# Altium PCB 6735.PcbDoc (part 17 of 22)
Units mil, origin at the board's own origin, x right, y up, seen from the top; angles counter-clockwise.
Board outline 2641.73 x 5165.35 mil, 6 copper layers (Top, Inner Layer 2, Inner Layer 3, Inner Layer 4, Inner Layer 5, Bottom), stack 35.7 mil thick; 1011 components, 790 nets, 4118 pads, 9325 vias.
Unrouted connection lines stored in the file: 4610.
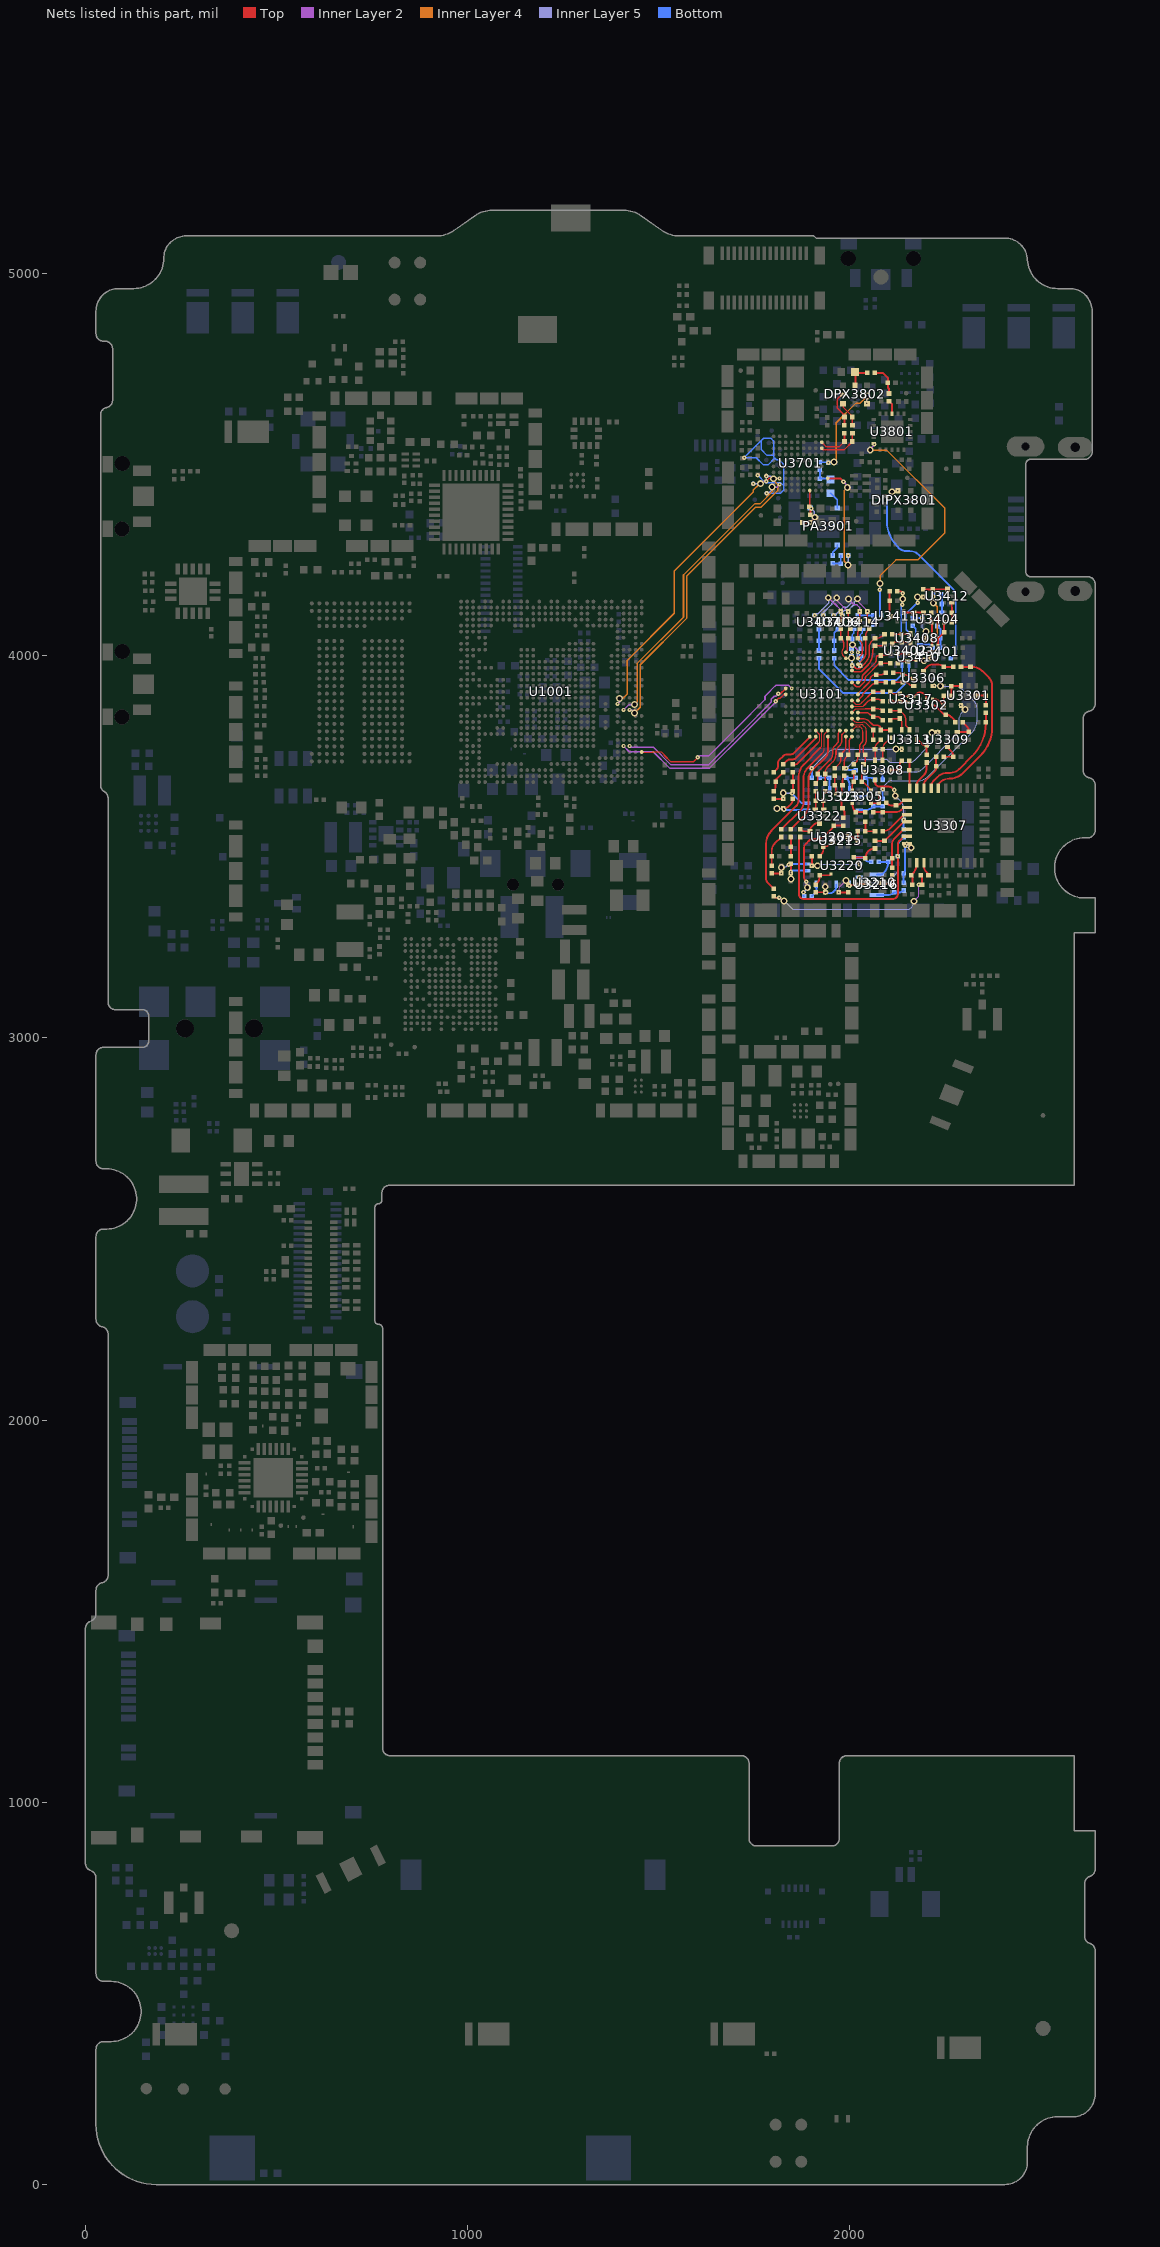
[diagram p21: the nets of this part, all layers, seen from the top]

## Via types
v1: diameter 12, hole 4, Top to Inner Layer 2, 3329 vias
v2: diameter 12, hole 4, Inner Layer 5 to Bottom, 3071 vias
v3: diameter 18, hole 10, Inner Layer 2 to Inner Layer 5, 1928 vias
v4: diameter 10, hole 4, Top to Inner Layer 2, 525 vias
v5: diameter 20, hole 12, Top to Bottom, 472 vias

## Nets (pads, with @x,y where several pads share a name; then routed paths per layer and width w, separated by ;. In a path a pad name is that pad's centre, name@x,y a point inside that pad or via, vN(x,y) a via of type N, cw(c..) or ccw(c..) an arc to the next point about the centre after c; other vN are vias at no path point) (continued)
RF_B1_PA_DPX: C3215.1 L3206.1 U3306.3 | length 529.8
  Top w5: U3306.3@2218.24,3920.9 v1(2221.24,3920.9)
  Inner Layer 2 w3: v1(2221.24,3920.9) 2221.24,3920.75 2236.65,3920.75 v3(2236.65,3920.59)
  Inner Layer 5 w3: v2(2085.65,3650.59) 2085.65,3651.59 cw(c2095.31,3651.59) 2088.48,3658.42 2098.17,3668.11 cw(c2109,3657.28) 2109,3672.59 2178.65,3672.59 ccw(c2178.65,3705.93) 2202.23,3682.36 2321.47,3801.6 ccw(c2294.48,3828.59) 2332.65,3828.59 2332.65,3863.59 ccw(c2310.92,3863.59) 2326.29,3878.95 2295.97,3909.28 ccw(c2268.65,3881.96) 2268.65,3920.59 v3(2236.65,3920.59)
  Bottom w5: L3206.1@2085.65,3625.59 v2(2085.65,3650.59)
RF_B1_PA_PA: C3216.1 L3206.2 U3203.25 | length 64
  Bottom w5: U3203.25@2024.55,3596.26 2041.65,3596.26 ccw(c2041.65,3619.6) 2058.16,3603.1 C3216.1@2060.65,3605.59 L3206.2@2085.65,3605.59
RF_B1_PRX_DPX_RFIN1: C3325.1 L3310.2 U3306.8 | length 57.8
  Top w4: C3325.1@2113.65,3955.59 2126.69,3955.59 cw(c2126.69,3938.79) 2138.57,3950.67 L3310.2@2138.65,3950.59 2143.65,3950.59 cw(c2143.65,3940.93) 2150.48,3947.76 2152.7,3945.54 ccw(c2164.65,3957.49) 2164.65,3940.59 U3306.8@2167.06,3940.59
RF_B1_PRX_DPX_RFIP1: C3323.1 L3310.1 U3306.1 | length 56.2
  Top w4: C3323.1@2113.65,3930.59 L3310.1@2138.65,3930.59 2145.65,3930.59 cw(c2145.65,3920.93) 2152.48,3927.76 2153.94,3926.3 ccw(c2166.97,3939.32) 2166.97,3920.9 U3306.1@2167.06,3920.9
RF_B1_PRX_MT6169_RFIN1_HB3: C3325.2 L3308.2 U3101.A8 | length 101
  Top w4: U3101.A8@2021.14,3898.59 2021.14,3901.08 2049.29,3929.23 ccw(c2039.92,3938.59) 2053.17,3938.59 2053.17,3939.59 cw(c2060.41,3939.59) 2055.29,3944.71 2057.29,3946.71 cw(c2066.65,3937.35) 2066.65,3950.59 L3308.2@2068.65,3950.59 2081.65,3950.59 ccw(c2081.65,3967.49) 2093.6,3955.54 C3325.2@2093.65,3955.59
RF_B1_PRX_MT6169_RFIP1_HB3: C3323.2 L3308.1 U3101.A9 | length 94.1
  Top w4: U3101.A9@2021.14,3882.84 2032.58,3894.28 ccw(c2029.74,3897.12) 2033.75,3897.12 2033.75,3898.59 cw(c2036.41,3898.59) 2034.53,3900.47 2057.82,3923.76 cw(c2064.65,3916.93) 2064.65,3926.59 L3308.1@2068.65,3930.59 C3323.2@2093.65,3930.59
RF_B1_TRX_DPX: L3309.2 L3311.1 U3306.6 | length 86.8
  Top w5: U3306.6@2192.65,3960.28 2192.65,3961.9 2193,3961.9 2203.31,3972.22 cw(c2213.87,3961.66) 2213.87,3976.59 2232.35,3976.59 cw(c2232.35,3958.95) 2244.82,3971.42 L3311.1@2245.65,3970.59 L3309.2@2270.65,3970.59
RF_B1_TRX_TXM: L3309.1 L3351.1 U3307.26 | length 446
  Top w5: U3307.26@2231.76,3653.03 2231.76,3664.59 2235.22,3668.06 cw(c2260.65,3642.62) 2260.65,3678.59 2261.65,3678.59 ccw(c2261.65,3726.87) 2295.8,3692.73 2341.39,3738.33 ccw(c2267.13,3812.59) 2372.15,3812.59 2372.15,3922.59 ccw(c2344.39,3922.59) 2364.02,3942.22 2346.26,3959.98 ccw(c2320.65,3934.38) 2320.65,3970.59 L3351.1@2315.65,3970.59 L3309.1@2290.65,3970.59
RF_B2_PA_DPX: C3222.1 L3207.1 U3301.3 | length 348.8
  Top w5: v1(2290.65,3870.59) 2290.97,3870.28 U3301.3@2290.97,3870
  Inner Layer 2 w3: v1(2290.65,3870.59) v3(2301.65,3859.59)
  Inner Layer 5 w3: v2(2085.65,3700.59) 2086.12,3700.13 ccw(c2094.65,3708.66) 2094.65,3696.59 2171.65,3696.59 ccw(c2171.65,3722.83) 2190.21,3704.28 2279.85,3793.92 ccw(c2263.42,3810.34) 2286.65,3810.34 2286.65,3837.59 cw(c2303.55,3837.59) 2291.6,3849.54 v3(2301.65,3859.59)
  Bottom w5: L3207.1@2085.65,3675.59 v2(2085.65,3700.59)
RF_B2_PA_PA: C3223.1 L3207.2 U3203.23 | length 94.8
  Bottom w5: U3203.23@2024.55,3630.9 2032.97,3630.9 ccw(c2032.97,3644.59) 2046.65,3644.59 2046.65,3674.59 C3223.1@2040.65,3680.59 2054.65,3680.59 cw(c2054.65,3666.1) 2064.9,3676.35 L3207.2@2065.65,3675.59
RF_B2_PRX_DPX: C3302.1 L3304.1 U3301.1 | length 50.6
  Top w5: C3302.1@2265.65,3895.59 L3304.1@2265.65,3920.59 2266.24,3921.18 U3301.1@2290.97,3921.18
RF_B2_PRX_SWITCH: C3302.2 L3302.1 U3302.3 | length 59.6
  Top w5: U3302.3@2216.4,3886.34 2218.65,3886.34 cw(c2218.65,3859.17) 2237.86,3878.38 L3302.1@2245.65,3870.59 C3302.2@2245.65,3895.59
RF_B2_TRX_DPX: C3303.2 L3303.1 U3301.6 | length 50.3
  Top w5: U3301.6@2330.34,3895.59 L3303.1@2355.65,3895.59 C3303.2@2355.65,3870.59
RF_B2_TRX_TXM: C3303.1 L3301.1 U3307.27 | length 268.7
  Top w5: U3307.27@2212.86,3653.03 2212.86,3657.59 cw(c2234.59,3657.59) 2219.22,3672.95 2228.69,3682.42 cw(c2255.65,3655.46) 2255.65,3693.59 2262.65,3693.59 ccw(c2262.65,3726.05) 2285.6,3703.1 2320.12,3737.62 ccw(c2234.35,3823.39) 2355.65,3823.39 L3301.1@2355.65,3825.59 C3303.1@2355.65,3850.59
RF_B2B3_PRX_BALUN: U3302.4 U3317.2 | length 47
  Top w5: U3317.2@2168.13,3893.46 2175.15,3900.48 cw(c2182.65,3892.98) 2182.65,3903.59 2183.65,3903.59 cw(c2183.65,3884.28) 2197.31,3897.93 2197.82,3897.42 cw(c2191,3890.59) 2200.65,3890.59 U3302.4@2200.65,3886.34
RF_B2B3_PRX_BALUN_RFIN1: C3307.1 L3305.1 U3317.3 | length 51
  Top w4: C3307.1@2105.65,3905.59 2106.41,3904.83 ccw(c2116.65,3915.08) 2116.65,3900.59 L3305.1@2130.65,3900.59 2131.84,3899.4 ccw(c2146.17,3913.73) 2146.17,3893.46 U3317.3@2153.17,3893.46
RF_B2B3_PRX_BALUN_RFIP1: C3311.1 L3305.2 U3317.4 | length 48.4
  Top w4: C3311.1@2105.65,3880.59 L3305.2@2130.65,3880.59 2147.65,3880.59 cw(c2147.65,3874.2) 2152.17,3878.72 U3317.4@2153.17,3877.72
RF_B2B3_PRX_MT6169_RFIN1_MB2: C3307.2 L3335.1 U3101.B9 | length 97.4
  Top w3: U3101.B9@2005.39,3882.84 2015.14,3873.09 2023.65,3873.09 ccw(c2023.65,3881.55) 2029.63,3875.57 2031.65,3877.59
  Top w4: 2031.65,3877.59 2059.65,3905.59 L3335.1@2060.65,3905.59 C3307.2@2085.65,3905.59
RF_B2B3_PRX_MT6169_RFIP1_MB2: C3311.2 L3335.2 U3101.B10 | length 88.2
  Top w3: U3101.B10@2005.39,3867.09 2030.24,3867.09 ccw(c2030.24,3876.55) 2036.93,3869.86 2037.65,3870.59
  Top w4: 2037.65,3870.59 2047.7,3880.64 cw(c2059.65,3868.69) 2059.65,3885.59 L3335.2@2060.65,3885.59 2074.65,3885.59 cw(c2074.65,3871.1) 2084.9,3881.35 C3311.2@2085.65,3880.59
RF_B3_DRX_MT6169_RFIN2_MB1: C3416.2 L3409.1 U3101.A2 | length 87.5
  Top w4: U3101.A2@2021.14,3993.08 2029.82,4001.76 ccw(c2023,4008.59) 2032.65,4008.59 2032.65,4025.59 ccw(c2015.75,4025.59) 2027.71,4037.53 2020.65,4044.59 L3409.1@2020.65,4045.59 2020.65,4058.59 cw(c2037.55,4058.59) 2025.6,4070.54 C3416.2@2025.65,4070.59
RF_B3_DRX_MT6169_RFIP2_MB1: C3412.2 L3409.2 U3101.A3 | length 103.9
  Top w4: U3101.A3@2021.14,3977.33 2034.05,3990.24 ccw(c2015.7,4008.59) 2041.65,4008.59 2041.65,4044.59 L3409.2@2040.65,4045.59 2040.65,4048.59 cw(c2069.62,4048.59) 2049.14,4069.08 C3412.2@2050.65,4070.59
RF_B3_DRX_SAW: C3414.2 L3414.2 U3406.1 | length 60.4
  Bottom w5: C3414.2@1959.15,4013.59 L3414.2@1959.15,4038.59 1959.15,4059.89 U3406.1@1969.15,4069.89
RF_B3_DRX_SAW_RFIN2: C3416.1 L3410.1 U3406.3 | length 154
  Top w3: L3410.1@2025.65,4115.59 2025.47,4115.81 2024.07,4117.51 2025.55,4115.86 2025.7,4115.69 2025.67,4116.1 2025.56,4117.5 v1(2025.84,4116.12)
  Top w4: C3416.1@2025.65,4090.59 L3410.1@2025.65,4115.59
  Inner Layer 2 w4: v3(1996.56,4148) 2011.56,4133 2018.75,4133 2025.3,4126.45 2025.3,4120.17 v1(2025.84,4116.12)
  Inner Layer 5 w4: v2(1957.48,4105.53) 1961.23,4105.53 1982.06,4126.36 1991.93,4126.36 2003.56,4138 2003.56,4141 v3(1996.56,4148)
  Bottom w4: v2(1957.48,4105.53) 1957.62,4105.53 U3406.3@1957.83,4105.32
RF_B3_DRX_SAW_RFIP2: C3412.1 L3410.2 U3406.4 | length 136.8
  Top w4: L3410.2@2045.65,4115.59 2045.65,4101.59 ccw(c2060.14,4101.59) 2049.9,4091.35 C3412.1@2050.65,4090.59
  Inner Layer 2 w4: v3(2020.06,4149) 2020.06,4143 2046.12,4116.95 v1(2046.12,4115.8)
  Inner Layer 5 w4: v2(1980.34,4105.13) 1980.34,4113.32 1985.38,4118.36 1995.24,4118.36 2011.56,4134.69 2011.56,4140.5 v3(2020.06,4149)
  Bottom w4: v2(1980.34,4105.13) 1980.34,4105.19 U3406.4@1980.47,4105.32
RF_B3_DRX_SWITCH: C3414.1 U3402.3 | length 243.7
  Bottom w5: C3414.1@1959.15,3993.59 1959.15,3974.44 1997.67,3935.93 2121.67,3935.93 2136.95,3951.22 U3402.3@2136.95,3975.65
RF_B3_PA_DPX: C3207.1 C3210.1 U3309.3 | length 322.8
  Inner Layer 2 w3: v3(2214.65,3798.59) 2216.34,3800.28 v1(2230.06,3800.28)
  Inner Layer 5 w3: v2(1990.65,3705.59) 2001.63,3716.57 cw(c2030.65,3687.55) 2030.65,3728.59 2093.65,3728.59 cw(c2093.65,3718.97) 2100.46,3725.77 2103.51,3722.72 ccw(c2108.65,3727.87) 2108.65,3720.59 2154.65,3720.59 ccw(c2154.65,3742.32) 2170.02,3726.95 2205.67,3762.6 ccw(c2183.97,3784.3) 2214.65,3784.3 v3(2214.65,3798.59)
  Bottom w5: v2(1990.65,3705.59) 1991.41,3704.83 ccw(c2001.65,3715.08) 2001.65,3700.59 C3207.1@2015.65,3700.59
RF_B3_PA_PA: C3207.2 C3211.1 U3203.21 | length 58.3
  Bottom w5: U3203.21@1998.96,3649.61 1998.96,3661.59 ccw(c1973.14,3661.59) 1991.4,3679.84 C3211.1@1990.65,3680.59 C3207.2@2015.65,3680.59
RF_B3_PRX_DPX: C3316.1 L3314.1 U3309.1 | length 60.2
  Top w5: U3309.1@2281.24,3800.28 2296.24,3800.28 2296.3,3800.21 2310.27,3800.21 L3314.1@2310.65,3800.59 2310.65,3804.59 ccw(c2296.17,3804.59) 2306.41,3814.83 C3316.1@2295.65,3825.59
RF_B3_PRX_SWITCH: C3316.2 L3313.1 U3302.2 | length 78.8
  Top w5: U3302.2@2216.4,3870.59 2217.65,3870.59 cw(c2217.65,3860.49) 2224.8,3867.63 2246.84,3845.59 L3313.1@2250.65,3845.59 2251.65,3845.59 cw(c2251.65,3826.95) 2264.83,3840.13 2275.65,3829.31 C3316.2@2275.65,3825.59
RF_B3_TRX_DPX: C3361.2 L3347.1 U3309.6 | length 55.9
  Top w5: C3361.2@2245.65,3735.59 L3347.1@2270.65,3735.59 2270.65,3735.94 ccw(c2249.21,3735.94) 2264.37,3751.1 2256.1,3759.38 2255.65,3759.38 U3309.6@2255.65,3760.9
RF_B3_TRX_TXM: C3361.1 C3362.1 U3307.28 | length 94.6
  Top w5: U3307.28@2193.96,3653.03 2193.96,3663.41 cw(c2207.2,3663.41) 2197.84,3672.78 2222.12,3697.05 ccw(c2213.58,3705.59) 2225.65,3705.59 C3362.1@2225.65,3710.59 C3361.1@2225.65,3735.59
RF_B5_DRX_MT6169_RFIN2_LB3: C3458.1 L3444.2 U3101.B1 | length 63.5
  Inner Layer 2 w4: v3(2004.15,3993.59) 2004.77,3993.59 2004.77,4008.83 v4(2005.39,4008.83)
  Inner Layer 5 w4: v3(2004.15,3993.59) 2006.65,3991.09 v2(2006.65,3973.59)
  Bottom w4: C3458.1@2004.15,3998.59 2004.15,3987.34 2006.65,3984.84 v2(2006.65,3973.59)
RF_B5_DRX_MT6169_RFIP2_LB3: C3459.1 L3444.1 U3101.A1 | length 115.1
  Inner Layer 2 w4: v3(2006.65,4028.59) 2021.14,4014.1 v4(2021.14,4008.83)
  Inner Layer 5 w4: v3(2006.65,4028.59) 2019.15,4016.09 2019.15,3991.98 2026.65,3984.48 v2(2026.65,3973.59)
  Bottom w4: v2(2026.65,3973.59) 2026.65,3984.84 2029.15,3987.34 C3459.1@2029.15,3998.59
RF_B5_DRX_SAW: C3460.2 L3433.1 U3414.1 | length 65
  Bottom w5: U3414.1@2021.65,4104.79 C3460.2@2061.65,4104.79 ; L3433.1@2061.65,4081.09 C3460.2@2061.65,4104.79 ; C3460.2@2061.65,4106.09 C3460.2@2061.65,4104.79
RF_B5_DRX_SAW_RFIN2: C3458.2 L3445.2 U3414.4 | length 53.3
  Bottom w4: C3458.2@2004.15,4018.59 2004.15,4029.84 2006.65,4032.34 L3445.2@2006.65,4043.59 2006.65,4055.17 2010.33,4058.85 U3414.4@2010.33,4069.36
RF_B5_DRX_SAW_RFIP2: C3459.2 L3445.1 U3414.3 | length 54.4
  Bottom w4: C3459.2@2029.15,4018.59 2029.15,4029.84 2026.65,4032.34 L3445.1@2026.65,4043.59 2026.65,4053.85 2032.97,4060.17 U3414.3@2032.97,4069.36
RF_B5_DRX_SWITCH: C3460.1 U3801.10 | length 665.2
  Top w4: U3801.10@2063.06,4554.59 2063.3,4554.35 v1(2063.3,4553.09)
  Inner Layer 2 w4: v3(2053.3,4538.09) 2052.05,4539.34 2064.55,4551.84 v1(2063.3,4553.09)
  Inner Layer 4 w4: v3(2053.3,4538.09) 2095.98,4538.09 2247.95,4386.12 2247.95,4321.31 2177.29,4250.65 2120.54,4250.65 2078.87,4208.97 v3(2078.87,4188.98)
  Inner Layer 5 w3: v2(2078.56,4173) 2078.85,4173.98 v3(2078.87,4188.98)
  Bottom w5: v2(2078.56,4173) 2078.85,4173 2078.85,4108.9 C3460.1@2081.65,4106.09
RF_B5_PA_DPX: C3260.1 L3217.1 U3313.3 | length 280.2
  Inner Layer 2 w3: v3(2120.65,3755.59) 2120.65,3755.29 2135.97,3755.29 v1(2135.97,3755)
  Inner Layer 5 w3: v2(1900.65,3705.59) 1940.75,3745.69 cw(c1964.65,3721.79) 1964.65,3755.59 v3(2120.65,3755.59)
  Bottom w5: L3217.1@1900.65,3680.59 v2(1900.65,3705.59)
RF_B5_PA_PA: C3257.1 L3217.2 U3203.18 | length 56.5
  Bottom w5: L3217.2@1920.65,3680.59 C3257.1@1945.65,3680.59 1946.99,3679.25 U3203.18@1946.99,3649.61
RF_B5_PRX_DPX_RFIN1: C3335.1 L3328.2 U3313.8 | length 84.7
  Top w4: C3335.1@2105.65,3855.59 L3328.2@2130.65,3855.59 2131.65,3855.59 2141.41,3845.83 cw(c2131.17,3835.59) 2145.65,3835.59 2145.65,3818.15 2155.65,3808.15 U3313.8@2155.65,3806.18
RF_B5_PRX_DPX_RFIP1: C3327.1 L3328.1 U3313.1 | length 57.4
  Top w4: C3327.1@2105.65,3830.59 2107.12,3832.05 cw(c2115.65,3823.52) 2115.65,3835.59 L3328.1@2130.65,3835.59 2130.88,3835.36 cw(c2118.6,3823.08) 2135.97,3823.08 U3313.1@2135.97,3806.18
RF_B5_PRX_MT6169_RFIN1_LB3: C3335.2 L3329.2 U3101.B11 | length 86.1
  Top w3: U3101.B11@2005.39,3851.35 2015.14,3861.09 2040.15,3861.09 2040.65,3860.59
  Top w4: 2040.65,3860.59 L3329.2@2060.65,3860.59 2075.65,3860.59 cw(c2075.65,3848.52) 2084.19,3857.05 C3335.2@2085.65,3855.59
RF_B5_PRX_MT6169_RFIP1_LB3: C3327.2 L3329.1 U3101.A11 | length 72.1
  Top w4: U3101.A11@2021.14,3851.35 2041.65,3851.35 cw(c2041.65,3836.86) 2051.9,3847.1 2058.41,3840.59 L3329.1@2060.65,3840.59 2071.92,3840.59 cw(c2071.92,3831.58) 2078.29,3837.95 C3327.2@2085.65,3830.59
RF_B5_TRX_DPX: C3330.2 L3330.1 U3313.6 | length 56
  Top w5: U3313.6@2175.34,3780.59 2176.96,3780.59 2176.96,3780.25 2186.65,3770.56 ccw(c2198.65,3782.57) 2198.65,3765.59 L3330.1@2200.65,3765.59 C3330.2@2200.65,3740.59
RF_B5_TRX_TXM: C3330.1 U3307.29 | length 76.5
  Top w5: U3307.29@2175.06,3653.03 2175.06,3663.65 cw(c2187.97,3663.65) 2178.84,3672.78 2192.87,3686.81 ccw(c2174.1,3705.59) 2200.65,3705.59 C3330.1@2200.65,3720.59
RF_B7_DRX_MT6169_RFIN2_HB2: C3419.2 L3416.2 U3101.B3 | length 146.5
  Top w4: U3101.B3@2005.39,3977.33 2015.55,3967.18 ccw(c2019.38,3971.01) 2019.38,3965.59 2022.48,3965.59 ccw(c2022.48,3971.31) 2026.52,3967.26 2039.31,3980.05 ccw(c2011.92,4007.44) 2050.65,4007.44 2050.65,4023.59 cw(c2069.97,4023.59) 2056.31,4037.25 2064.65,4045.59 L3416.2@2065.65,4045.59 2066.63,4045.59 ccw(c2066.63,4079.45) 2090.57,4055.51 C3419.2@2090.65,4055.59
RF_B7_DRX_MT6169_RFIP2_HB2: C3420.2 L3416.1 U3101.B4 | length 131.6
  Top w4: U3101.B4@2005.39,3961.58 2005.66,3961.31 ccw(c2014.65,3970.31) 2014.65,3957.59 2025.65,3957.59 ccw(c2025.65,3967.06) 2032.35,3960.36 2046.98,3975 ccw(c2016.39,4005.59) 2059.65,4005.59 2059.65,4011.59 cw(c2078.97,4011.59) 2065.31,4025.25 L3416.1@2065.65,4025.59 2079.65,4025.59 ccw(c2079.65,4040.08) 2089.9,4029.83 C3420.2@2090.65,4030.59
RF_B7_DRX_SAW: C3418.2 L3415.1 U3408.1 | length 84.5
  Top w5: v1(2194.16,4046.8) 2194.35,4046.6 U3408.1@2194.35,4045.59
  Inner Layer 2 w3: v1(2194.16,4046.8) 2199.48,4052.12 v3(2199.48,4063.56)
  Inner Layer 5 w3: v2(2189.72,4098.72) 2189.72,4073.33 v3(2199.48,4063.56)
  Bottom w5: C3418.2@2164.15,4098.59 L3415.1@2189.15,4098.59
RF_B7_DRX_SAW_RFIN2: C3419.1 L3417.1 U3408.3 | length 48.8
  Top w4: C3419.1@2110.65,4055.59 2135.55,4055.59 L3417.1@2135.65,4055.59 2157.6,4055.59 U3408.3@2158.92,4056.91
RF_B7_DRX_SAW_RFIP2: C3420.1 L3417.2 U3408.4 | length 50.4
  Top w4: C3420.1@2110.65,4030.59 2112.12,4032.05 cw(c2120.65,4023.52) 2120.65,4035.59 L3417.2@2135.65,4035.59 2137.53,4035.59 2157.6,4035.59 U3408.4@2158.92,4034.27
RF_B7_DRX_SWITCH: C3418.1 U3402.11 | length 31.4
  Bottom w5: C3418.1@2164.15,4078.59 2172.39,4070.36 U3402.11@2172.39,4050.65
RF_B7_PA_DPX: C3255.1 L3209.2 U3308.3 | length 177.6
  Top w5: U3308.3@2065.97,3675 2065.97,3668.59 ccw(c2076.97,3668.59) 2076.97,3657.59 2100.65,3657.59 cw(c2100.65,3643.1) 2110.9,3653.35 v1(2115.65,3648.59)
  Inner Layer 2 w3: v1(2115.65,3648.59) 2115.65,3636.59 v3(2118.65,3633.59)
  Inner Layer 5 w3: v3(2118.65,3633.59) 2132.17,3620.08 cw(c2111.68,3599.59) 2140.65,3599.59 v2(2140.65,3570.59)
  Bottom w5: L3209.2@2140.65,3545.59 v2(2140.65,3570.59)
RF_B7_PA_PA: C3289.1 L3209.1 U3203.35 | length 230.7
  Inner Layer 5 w3: v2(2024.55,3420.28) 2033.31,3411.51 ccw(c2047.61,3425.81) 2047.61,3405.59 2090.65,3405.59 ccw(c2090.65,3422.49) 2102.6,3410.54 2120,3427.93 ccw(c2106.34,3441.59) 2125.65,3441.59 v2(2125.65,3475.59)
  Bottom w5: v2(2125.65,3475.59) 2125.65,3501.59 ; L3209.1@2140.65,3525.59 2132.02,3516.95 ; 2125.65,3501.59 cw(c2147.38,3501.59) 2132.02,3516.95 ; 2125.65,3501.59 cw(c2147.38,3501.59) 2132.02,3516.95
RF_B7_PRX_DPX_RFIN1: C3321.1 L3316.2 U3308.8 | length 66.8
  Top w4: U3308.8@2085.65,3726.18 L3316.2@2085.65,3755.59 cw(c2107.38,3755.59) 2092.02,3770.95 2105.65,3784.59 C3321.1@2105.65,3785.59
RF_B7_PRX_DPX_RFIP1: C3315.1 L3316.1 U3308.1 | length 60
  Top w4: U3308.1@2065.97,3726.18 2065.97,3755.28 L3316.1@2065.65,3755.59 2065.65,3757.04 cw(c2083.87,3757.04) 2070.99,3769.93 2080.65,3779.59 C3315.1@2080.65,3780.59
RF_B7_PRX_MT6169_RFIN1_HB2: C3321.2 L3312.2 U3101.A12 | length 99
  Top w4: U3101.A12@2021.14,3835.6 2032.65,3835.6 cw(c2032.65,3809.72) 2050.95,3828.02 2058.57,3820.4 ccw(c2065.35,3827.18) 2065.35,3817.59 2072.65,3817.59 cw(c2072.65,3809.59) 2080.65,3809.59 L3312.2@2080.65,3805.59 C3321.2@2105.65,3805.59
RF_B7_PRX_MT6169_RFIP1_HB2: C3315.2 L3312.1 U3101.B12 | length 92.3
  Top w3: U3101.B12@2005.39,3835.6 2005.11,3835.32 2011.85,3828.58 ccw(c2017.65,3834.39) 2017.65,3826.18 2034.31,3826.18 cw(c2034.31,3812.29) 2044.13,3822.11 2044.65,3821.59
  Top w4: 2044.65,3821.59 L3312.1@2060.65,3805.59 C3315.2@2060.65,3780.59
RF_B7_TRX_DPX: C3317.2 L3315.1 U3308.6 | length 51.9
  Top w5: U3308.6@2105.34,3700.59 L3315.1@2130.65,3700.59 2130.65,3715.59 cw(c2142.72,3715.59) 2134.19,3724.13 C3317.2@2135.65,3725.59
RF_B7_TRX_TXM: C3317.1 L3318.1 U3307.30 | length 72.8
  Top w5: C3317.1@2155.65,3725.59 L3318.1@2155.65,3700.59 2156.16,3700.08 U3307.30@2156.16,3653.03
RF_B34_PRX_SAW: C3343.2 L3338.1 U3305.4 | length 47.2
  Top w5: U3305.4@2055.16,3613.86 2075.65,3613.86 C3343.2@2075.65,3615.59 L3338.1@2075.65,3640.59
RF_B34_PRX_TXM: C3343.1 L3342.1 U3307.31 | length 60.8
  Top w5: C3343.1@2095.65,3615.59 2099.12,3612.13 ccw(c2107.65,3620.66) 2107.65,3608.59 L3342.1@2120.65,3608.59 2120.98,3608.59 ccw(c2120.98,3624.35) 2132.13,3613.21 2140.65,3621.73 U3307.31@2149.27,3621.73
RF_B34B39_PA_LPF_IN: C3206.2 L3214.1 U3216.1 | length 76.5
  Bottom w5: U3216.1@2070.65,3427.66 2083.94,3427.66 2089.47,3433.18 ccw(c2062.46,3460.19) 2100.65,3460.19 L3214.1@2100.65,3460.59 C3206.2@2075.65,3460.59
RF_B34B39_PA_LPF_OUT: C3276.1 L3223.1 U3216.3 | length 73.3
  Bottom w5: U3216.3@2070.65,3373.52 2099.65,3373.52 ccw(c2099.65,3395.09) 2114.9,3379.84 L3223.1@2115.65,3380.59 2128.65,3380.59 ccw(c2128.65,3397.49) 2140.6,3385.54 C3276.1@2140.65,3385.59
RF_B34B39_PA_PA: C3206.1 U3203.32 | length 34.9
  Bottom w5: U3203.32@2024.55,3472.24 2033.05,3472.24 2037.66,3467.63 ccw(c2054.65,3484.62) 2054.65,3460.59 C3206.1@2055.65,3460.59
RF_B34B39_PA_TXM: C3276.2 L3234.1 U3307.37 | length 131.6
  Inner Layer 2 w3: v1(2149.27,3508.35) 2149.43,3508.5 2160.5,3497.43 v3(2160.65,3497.59)
  Inner Layer 5 w3: v2(2144.65,3502.59) 2145.54,3501.7 ccw(c2155.47,3511.63) 2155.47,3497.59 v3(2160.65,3497.59)
  Bottom w5: C3276.2@2140.65,3405.59 L3234.1@2140.65,3430.59 ccw(c2131,3440.24) 2144.65,3440.24 v2(2144.65,3502.59)
RF_B34B39_PRX_MT6169_RFIN1_MB1: C3344.2 L3336.1 U3101.B13 | length 141
  Top w3: U3101.B13@2005.39,3819.85 2028.65,3819.85 cw(c2028.65,3810.19) 2035.48,3817.02 2040.35,3812.15 cw(c2034.78,3806.59) 2042.65,3806.59 2042.65,3803.59
  Top w4: C3344.2@2035.65,3715.59 2036.41,3716.35 ccw(c2026.17,3726.59) 2040.65,3726.59 L3336.1@2040.65,3740.59 2036.77,3744.47 cw(c2041.9,3749.59) 2034.65,3749.59 2034.65,3761.59 cw(c2039.48,3761.59) 2036.07,3765 2038.41,3767.35 ccw(c2028.17,3777.59) 2042.65,3777.59 2042.65,3803.59
RF_B34B39_PRX_MT6169_RFIP1_MB1: C3341.2 L3336.2 U3101.B14 | length 132.8
  Top w3: U3101.B14@2005.39,3804.1 2012.92,3811.63 cw(c2017.65,3806.9) 2017.65,3813.59 2024.65,3813.59 cw(c2024.65,3808.76) 2028.06,3812.18 2030.82,3809.42 cw(c2024,3802.59) 2033.65,3802.59 2033.65,3800.59
  Top w4: C3341.2@2010.65,3715.59 2015.86,3720.8 ccw(c2004.29,3732.37) 2020.65,3732.37 L3336.2@2020.65,3740.59 2023.41,3743.35 ccw(c2017.99,3748.76) 2025.65,3748.76 2025.65,3762.47 cw(c2037.35,3762.47) 2029.08,3770.74 2031.34,3773 ccw(c2025.75,3778.59) 2033.65,3778.59 2033.65,3800.59
RF_B34B39_PRX_SAW_RFIN1: C3344.1 L3337.1 U3305.6 | length 61.7
  Top w4: C3344.1@2035.65,3695.59 2034.19,3694.13 ccw(c2042.72,3685.59) 2030.65,3685.59 L3337.1@2030.65,3670.59 2033.65,3670.59 2055.16,3649.08 U3305.6@2055.16,3647.32
RF_B34B39_PRX_SAW_RFIP1: C3341.1 L3337.2 U3305.9 | length 49.5
  Top w4: U3305.9@2006.14,3647.32 2006.14,3659.77 cw(c2021.38,3659.77) 2010.61,3670.54 L3337.2@2010.65,3670.59 C3341.1@2010.65,3695.59
RF_B39_DRX_MT6169_RFIN2_MB2: C3417.2 L3413.1 U3101.C2 | length 85.3
  Top w3: 1983.65,4022.59 1983.65,4020.59 cw(c1978.82,4020.59) 1982.25,4017.18 1981.48,4016.42 ccw(c1985.31,4012.59) 1979.9,4012.59 1979.9,4004.59 ccw(c1984.16,4004.59) 1981.14,4001.58 U3101.C2@1989.64,3993.08
  Top w4: C3417.2@1975.65,4070.59 L3413.1@1975.65,4045.59 1980.12,4041.13 cw(c1971.58,4032.59) 1983.65,4032.59 1983.65,4022.59
RF_B39_DRX_MT6169_RFIP2_MB2: C3413.2 L3413.2 U3101.C1 | length 65.5
  Top w4: U3101.C1@1989.64,4008.83 1990.04,4009.22 ccw(c1983.73,4015.53) 1992.65,4015.53 1992.65,4042.59 L3413.2@1995.65,4045.59 1995.65,4061.59 cw(c2005.31,4061.59) 1998.48,4068.42 C3413.2@2000.65,4070.59
RF_B39_DRX_SAW: C3415.2 L3411.2 U3407.1 | length 56.3
  Bottom w5: C3415.2@1919.15,4013.59 L3411.2@1919.15,4038.59 U3407.1@1919.15,4069.89
RF_B39_DRX_SAW_RFIN2: C3417.1 L3412.1 U3407.3 | length 140.1
  Top w4: C3417.1@1975.65,4090.59 v1(1975.65,4115.59)
  Inner Layer 2 w4: v3(1943.56,4151.5) 1944.15,4151.69 1944.15,4151.09 1950.55,4144.69 1951.16,4144.69 1959.35,4136.5 1959.85,4136.5 1960.35,4136 1975.65,4120.7 v1(1975.65,4115.59)
  Inner Layer 5 w4: v2(1908.31,4105.41) 1912.73,4109.83 1916.81,4109.83 1944.15,4137.18 1944.15,4151.69 v3(1943.56,4151.5)
  Bottom w4: U3407.3@1907.83,4105.32 1907.92,4105.41 v2(1908.31,4105.41)
RF_B39_DRX_SAW_RFIP2: C3413.1 L3412.2 U3407.4 | length 136.6
  Top w4: v1(1995.65,4115.59) 1995.65,4100.59 ccw(c2007.72,4100.59) 1999.19,4092.05 C3413.1@2000.65,4090.59
  Inner Layer 2 w4: v3(1965.56,4151.5) 1966.56,4151 1966.65,4151.09 1966.65,4144.59 v1(1995.65,4115.59)
  Inner Layer 5 w4: v2(1930.47,4105.32) 1930.47,4112.19 1952.16,4133.87 1952.16,4136.59 1966.31,4150.75 v3(1965.56,4151.5)
RF_B39_DRX_SWITCH: C3415.1 U3402.2 | length 343
  Bottom w5: C3415.1@1919.15,3993.59 1919.15,3965.26 1981.51,3902.89 2092.48,3902.89 ; 2092.49,3902.91 2115.03,3902.91 2121.47,3902.89 2154.67,3936.09 U3402.2@2154.67,3975.65
RF_B39_PRX_SAW: C3342.2 L3332.2 U3305.1 | length 50.8
  Top w5: U3305.1@2006.14,3613.86 2006.14,3613.19 ccw(c2037.76,3613.19) 2015.4,3590.84 L3332.2@2015.65,3590.59 C3342.2@2040.65,3590.59
RF_B39_PRX_TXM: C3342.1 L3340.2 U3307.32 | length 92.8
  Top w5: C3342.1@2060.65,3590.59 L3340.2@2085.65,3590.59 2119.74,3590.59 ccw(c2119.74,3611.51) 2134.54,3596.72 2140.65,3602.83 U3307.32@2149.27,3602.83
RF_B40_DRX_SAW: C3432.2 L3402.2 U3404.1 | length 59.4
  Bottom w5: U3404.1@2229.26,4077.46 2236.65,4070.07 L3402.2@2236.65,4046.09 C3432.2@2236.65,4021.09
RF_B40_DRX_SAW_1: C3455.1 L3442.2 U3404.4 | length 48.7
  Bottom w5: C3455.1@2238.31,4160.65 2240.57,4158.39 L3442.2@2240.57,4135.24 2240.57,4123.39 ; U3404.4@2240.58,4112.89 2240.58,4123.38
RF_B40_DRX_SWITCH: C3432.1 U3402.12 | length 36.6
  Bottom w5: U3402.12@2183.31,4028.9 2208.84,4028.9 C3432.1@2216.65,4021.09
RF_B40_DRX_SWITCH_1: C3455.2 U3401.5 | length 220.6
  Top w4: v1(2210.99,3993.46) 2214.9,3993.46 U3401.5@2214.9,3994.84
  Inner Layer 2 w3: v3(2193.66,3986.92) 2200.19,3993.46 v1(2210.99,3993.46)
  Inner Layer 4 w4: v3(2193.66,3986.92) 2197.68,3986.92 2228.48,4017.72 2228.48,4127.98 v3(2218.31,4138.15)
  Inner Layer 5 w3: v3(2218.31,4138.15) 2218.44,4138.15 2218.44,4154.95 v2(2218.56,4154.95)
  Bottom w5: C3455.2@2218.31,4160.65 2218.56,4160.65 v2(2218.56,4154.95)
RF_B40_TRX_1: C3286.1 C3288.2 L3222.2 | length 50
  Top w5: L3222.2@2040.65,3565.59 C3288.2@2040.65,3540.59 C3286.1@2065.65,3540.59
RF_B40_TRX_BAW_IN: C3259.1 L3210.2 U3215.1 | length 59
  Top w5: L3210.2@1920.65,3475.59 1924.36,3479.29 ccw(c1909.15,3494.5) 1930.65,3494.5 C3259.1@1930.65,3500.59 1933.65,3500.59 ccw(c1933.65,3518.25) 1946.14,3505.76 U3215.1@1955.97,3515.59
RF_B40_TRX_BAW_OUT: C3288.1 L3221.2 U3215.4 | length 53.7
  Top w5: U3215.4@1995.34,3526.91 1996.65,3526.91 cw(c1996.65,3496.29) 2018.3,3517.94 L3221.2@2020.65,3515.59 C3288.1@2020.65,3540.59
RF_B40_TRX_PA: C3258.1 L3210.1 U3203.33 | length 150.5
  Top w5: v1(1900.52,3450.6) C3258.1@1900.65,3450.59 L3210.1@1900.65,3475.59
  Inner Layer 2 w3: v1(1900.52,3450.6) v3(1915.65,3450.59)
  Inner Layer 5 w3: v3(1915.65,3450.59) 1916.68,3451.62 cw(c1924.65,3443.65) 1924.65,3454.92 v2(2024.55,3454.92)
RF_B40_TRX_TXM: C3286.2 U3307.33 | length 80.4
  Top w5: C3286.2@2085.65,3540.59 2086.65,3540.59 ccw(c2086.65,3567.17) 2105.44,3548.37 2141.01,3583.94 U3307.33@2149.27,3583.94
RF_B40B41_PRX_BALUN: C3352.2 L3350.1 U3323.2 | length 49.8
  Top w5: U3323.2@1978.53,3623.11 1978.53,3602.72 L3350.1@1980.65,3600.59 1981.41,3599.83 cw(c1971.17,3589.59) 1985.65,3589.59 C3352.2@1985.65,3575.59
RF_B40B41_PRX_BALUN_RFIN1: C3353.1 L3343.1 U3323.3 | length 49.7
  Top w4: U3323.3@1978.53,3638.07 1978.53,3658.46 L3343.1@1980.65,3660.59 1980.65,3673.6 cw(c1997.53,3673.6) 1985.6,3685.53 C3353.1@1985.65,3685.59
RF_B40B41_PRX_BALUN_RFIP1: C3349.1 L3343.2 U3323.4 | length 48.4
  Top w4: C3349.1@1960.65,3685.59 L3343.2@1960.65,3660.59 1962.78,3658.46 U3323.4@1962.78,3638.07
RF_B40B41_PRX_MT6169_RFIN1_HB1: C3353.2 L3341.1 U3101.B15 | length 89.6
  Top w4: C3353.2@1985.65,3705.59 1985.65,3722.59 cw(c2004.97,3722.59) 1991.31,3736.25 L3341.1@1995.65,3740.59 1998.65,3743.59 1998.65,3776.59 cw(c2010.78,3776.59) 2002.21,3785.17 U3101.B15@2005.39,3788.35
RF_B40B41_PRX_MT6169_RFIP1_HB1: C3349.2 L3341.2 U3101.C15 | length 93.9
  Top w4: C3349.2@1960.65,3705.59 1971.41,3716.35 ccw(c1961.17,3726.59) 1975.65,3726.59 L3341.2@1975.65,3740.59 L3341.2@1975.65,3741.09 ; U3101.C15@1989.64,3788.35 1989.64,3763.51 cw(c1970.52,3763.51) 1984.04,3749.99 L3341.2@1975.65,3741.6 ; L3341.2@1975.65,3741.09 1975.51,3741.45 L3341.2@1975.65,3741.6 ; L3341.2@1975.65,3741.09 L3341.2@1975.65,3741.6
RF_B40B41_PRX_PA: C3261.2 U3203.42 | length 35.1
  Bottom w5: C3261.2@1900.65,3370.59 1907.33,3377.27 ccw(c1895.22,3389.38) 1912.35,3389.38 U3203.42@1912.35,3401.57
RF_B40B41_PRX_PA_1: C3261.1 C3352.1 L3344.2 | length 266.2
  Top w5: v1(1885.65,3408.59) 1885.56,3408.68 cw(c1899.83,3422.95) 1879.65,3422.95 1879.65,3494.59 cw(c1898.97,3494.59) 1885.31,3508.25 1892.7,3515.64 cw(c1904.65,3503.69) 1904.65,3520.59 1913.65,3520.59 ccw(c1913.65,3549.56) 1934.14,3529.08 1960.65,3555.59 C3352.1@1983.15,3555.59 C3352.1@1985.65,3555.59
  Inner Layer 2 w3: v1(1885.65,3408.59) 1885.65,3396.59 v3(1888.65,3393.59)
  Inner Layer 5 w4: v2(1878.65,3380.59) 1888.65,3390.59 v3(1888.65,3393.59)
  Bottom w4: v2(1878.65,3380.59) 1878.65,3370.59 C3261.1@1880.65,3370.59
RF_B40B41_TRX_LPF_IN: C3265.1 L3211.2 U3210.2 | length 52.4
  Top w5: L3211.2@1995.65,3400.59 C3265.1@2020.65,3400.59 2023.19,3403.12 2043.5,3403.12 U3210.2@2045.97,3405.59
RF_B40B41_TRX_LPF_OUT: C3262.1 C3264.1 U3210.5 | length 52.4
  Top w5: U3210.5@2085.34,3405.59 2087.8,3403.12 2108.12,3403.12 C3264.1@2110.65,3400.59 C3262.1@2110.65,3425.59
RF_B40B41_TRX_PA_BYPASS: C3263.1 L3211.1 U3203.37 | length 85.2
  Top w5: v1(1970.65,3380.59) L3211.1@1995.65,3380.59
  Inner Layer 2 w3: v1(1970.65,3380.59) 1970.65,3385.61 cw(c1987.51,3385.61) 1975.59,3397.53 v3(1989.65,3411.59)
  Inner Layer 5 w4: v3(1989.65,3411.59) 1989.65,3406.57 1998.65,3397.57 v2(1998.96,3397.57)
  Bottom w5: v2(1998.96,3397.57) U3203.37@1998.96,3401.57
RF_B40B41_TRX_TXM_BYPASS: C3262.2 C3271.1 U3307.35 | length 120.7
  Top w5: C3262.2@2110.65,3445.59 C3271.1@2110.65,3470.59 2110.65,3508.59 cw(c2128.03,3508.59) 2115.74,3520.87 2141.01,3546.14 U3307.35@2149.27,3546.14
RF_B41_DRX_BALUN: U3401.4 U3410.2 | length 28.9
  Top w5: U3410.2@2188.13,4003.46 2189.32,4004.65 cw(c2203.65,3990.33) 2203.65,4010.59 U3401.4@2214.9,4010.59
RF_B41_DRX_BALUN_RFIN2: C3454.1 L3440.2 U3410.3 | length 48.4
  Top w4: C3454.1@2125.65,4005.59 L3440.2@2150.65,4005.59 2152.78,4003.46 U3410.3@2173.17,4003.46
RF_B41_DRX_BALUN_RFIP2: C3453.1 L3440.1 U3410.4 | length 50.2
  Top w4: C3453.1@2125.65,3980.59 2128.53,3983.47 cw(c2133.65,3978.35) 2133.65,3985.59 L3440.1@2150.65,3985.59 2152.78,3987.72 U3410.4@2173.17,3987.72
RF_B41_DRX_MT6169_RFIN2_HB1: C3454.2 L3439.2 U3101.A6 | length 127.3
  Top w4: U3101.A6@2021.14,3930.09 2025.15,3930.09 2030.53,3935.47 ccw(c2025.41,3940.59) 2032.65,3940.59 2032.65,3944.59 cw(c2040.35,3944.59) 2034.91,3950.04 2065.96,3981.09 ccw(c2059.45,3987.59) 2068.65,3987.59 2068.65,3994.59 cw(c2074.65,3994.59) 2074.65,4000.59 L3439.2@2080.65,4000.59 2093.65,4000.59 ccw(c2093.65,4017.49) 2105.6,4005.54 C3454.2@2105.65,4005.59
RF_B41_DRX_MT6169_RFIP2_HB1: C3453.2 L3439.1 U3101.B6 | length 135.6
  Top w4: U3101.B6@2005.39,3930.09 2015.64,3919.84 ccw(c2018.65,3922.85) 2018.65,3918.59 2022.65,3918.59 ccw(c2022.65,3924.47) 2026.81,3920.31 2036.86,3930.36 ccw(c2027.72,3939.51) 2040.65,3939.51 2040.65,3942.59 cw(c2045.18,3942.59) 2041.98,3945.79 2076.78,3980.59 L3439.1@2080.65,3980.59 C3453.2@2105.65,3980.59
RF_B41_DRX_SAW_IN_A: C3433.2 L3430.2 U3411.1 | length 66.5
  Top w5: C3433.2@2104.15,4168.59 L3430.2@2104.15,4143.59 2104.15,4103.89 U3411.1@2105.45,4102.59
RF_B41_DRX_SAW_IN_B: C3421.2 L3418.1 U3412.1 | length 63.6
  Top w5: C3421.2@2191.65,4173.59 L3418.1@2216.65,4173.59 2235.36,4173.59 2235.56,4173.79 U3412.1@2255.15,4173.79
RF_B41_DRX_SAW_OUT_A: C3434.1 L3429.2 U3411.4 | length 52.3
  Top w5: U3411.4@2140.89,4113.91 2142.2,4112.59 L3429.2@2167.65,4112.59 C3434.1@2192.65,4112.59
RF_B41_DRX_SAW_OUT_B: C3436.1 L3431.2 U3412.4 | length 50.8
  Top w5: U3412.4@2266.47,4138.36 2266.47,4126.1 2266.65,4125.92 L3431.2@2266.65,4112.59 C3436.1@2266.65,4087.59
RF_B41_DRX_SWITCH_A: C3433.1 U3402.9 | length 134
  Top w5: C3433.1@2124.15,4168.59 2132.87,4168.59 v1(2138.31,4163.15)
  Inner Layer 2 w3: v3(2138.31,4148.15) v1(2138.31,4163.15)
  Inner Layer 5 w3: v2(2136.81,4133.15) 2137.56,4133.15 2137.56,4148.15 v3(2138.31,4148.15)
  Bottom w5: v2(2136.81,4133.15) 2134.31,4133.15 2134.31,4060.4 2136.95,4057.76 U3402.9@2136.95,4050.65
RF_B41_DRX_SWITCH_A_1: C3434.2 L3437.2 U3401.3 | length 87.2
  Top w5: C3434.2@2212.65,4112.59 L3437.2@2212.65,4087.59 2214.9,4085.34 U3401.3@2214.9,4026.34
RF_B41_DRX_SWITCH_B: C3421.1 U3402.10 | length 135
  Inner Layer 2 w3: v3(2176.56,4153.5) 2176.65,4153.59 v1(2191.65,4153.59)
  Inner Layer 5 w3: v3(2176.56,4153.5) 2176.65,4153.59 2176.48,4153.59 2176.48,4138.15 2176.31,4138.15 v2(2177.06,4138)
  Bottom w5: U3402.10@2154.67,4050.65 2154.67,4061.07 2147.41,4068.33 2147.41,4109.25 2176.31,4138.15 v2(2177.06,4138)
RF_B41_DRX_SWITCH_B_1: C3436.2 L3441.2 U3401.2 | length 67.9
  Top w5: U3401.2@2230.65,4026.34 2230.65,4045.59 L3441.2@2246.65,4061.59 C3436.2@2246.65,4087.59
RF_B41_TRX_FBAR_IN: C3273.1 L3213.2 U3220.1 | length 59.8
  Top w5: L3213.2@1910.65,3400.59 1912.47,3402.41 ccw(c1892.72,3422.16) 1920.65,3422.16 C3273.1@1920.65,3425.59 1947.78,3425.59 U3220.1@1951.13,3428.94
RF_B41_TRX_FBAR_OUT: C3285.1 L3218.2 U3220.2 | length 70.6
  Top w5: U3220.2@2010.18,3472.24 2039,3472.24 L3218.2@2040.65,3470.59 2040.65,3471.59 cw(c2062.38,3471.59) 2047.02,3486.95 2049.8,3489.74 cw(c2063.93,3475.6) 2063.93,3495.59 C3285.1@2065.65,3495.59
RF_B41_TRX_PA: C3272.1 L3213.1 U3203.39 | length 100.4
  Top w4: L3213.1@1910.65,3380.59 C3272.1@1935.65,3380.59 v1(1935.65,3380.41)
  Inner Layer 2 w3: v1(1935.65,3380.41) v3(1935.65,3395.59)
  Inner Layer 5 w4: v3(1935.65,3395.59) 1937.15,3395.59 1937.15,3380.59 v2(1938.65,3380.59)
  Bottom w5: v2(1938.65,3380.59) 1940.65,3378.59 1948.6,3378.59 ccw(c1948.6,3389.98) 1956.65,3381.93 1960.81,3386.08 ccw(c1952.34,3394.55) 1964.31,3394.55 U3203.39@1964.31,3401.57
RF_B41_TRX_TXM: C3285.2 L3219.2 U3307.34 | length 104.1
  Top w5: C3285.2@2065.65,3515.59 L3219.2@2090.65,3515.59 2091.56,3515.59 2141.01,3565.04 U3307.34@2149.27,3565.04
RF_BC0_PA_DPX: DPX3802.3 L3822.1 R3817.1 | length 273.1
  Top w5: v1(2044.3,4661.09) v1(2044.3,4661.09) DPX3802.3@2044.35,4659.18
  Inner Layer 2 w4: v1(2044.3,4661.09) 2044.3,4678.09 v3(2045.3,4679.09)
  Inner Layer 4 w4: v3(1958.31,4507.09) 1964.31,4513.09 1964.31,4609.21 2016.19,4661.09 2027.3,4661.09 v3(2045.3,4679.09)
  Inner Layer 5 w4: v2(1943.31,4505.09) 1945.31,4507.09 v3(1958.31,4507.09)
  Bottom w5: R3817.1@1921.31,4506.09 1922.31,4506.09 1942.31,4506.09 v2(1943.31,4505.09)
RF_BC0_PA_MT6158: PA3901.6 R3701.2 R3702.1 | length 71.7
  Top w4: R3701.2@1875.31,4348.24 R3701.2@1875.5,4348.42
  Top w5: v1(1896.56,4348.49) R3702.1@1896.5,4348.42 R3701.2@1875.5,4348.42 ; R3701.2@1875.5,4348.42 1875.5,4348.9 1875.31,4348.72 1875.31,4348.24 1875.31,4347.09 R3701.2@1875.5,4348.42
  Inner Layer 2 w4: v1(1896.56,4348.49) 1896.1,4348.95 1907.78,4360.63 1907.32,4361.08 v3(1908.31,4362.09)
  Inner Layer 5 w4: v2(1899.08,4385.11) 1907.31,4376.87 1907.31,4362.09 v3(1908.31,4362.09)
RF_BC0_PA_MT6158_1: R3702.2 R3703.2 U3701.D10 | length 67.1
  Top w5: U3701.D10@1894.93,4432.22 1894.94,4391.23 1895.31,4390.85 R3703.2@1893.95,4389.49 1896.5,4389.49 R3702.2@1896.5,4368.42
RF_BC0_PA_PA: C3907.1 PA3901.9 | length 46.1
  Bottom w5: C3907.1@1949.31,4425.09 1966.94,4407.46 PA3901.9@1966.93,4386.34
RF_BC0_PA_PA_1: C3907.2 L3815.1 R3817.2 | length 51.8
  Bottom w5: R3817.2@1921.31,4486.09 L3815.1@1921.31,4463.09 1947.31,4463.09 C3907.2@1949.31,4461.09
RF_BC0_PRX_DPX_LNA_LB_RXN: C3808.1 DPX3802.1 L3819.2 | length 83.4
  Top w4: DPX3802.1@1983.95,4656.78 DPX3802.1@1982.34,4658.39 ; L3819.2@2002.95,4627.49 L3819.2@2005.95,4624.49 ; C3808.1@2006.95,4602.49 2005.95,4603.49 L3819.2@2005.95,4624.49 ; DPX3802.1@1981.55,4659.18 1982.34,4659.18 DPX3802.1@1982.34,4658.39 ; DPX3802.1@1981.55,4659.18 1979.3,4656.92 DPX3802.1@1981.56,4659.18 ; DPX3802.1@1981.56,4659.18 DPX3802.1@1982.34,4658.39 ; DPX3802.1@1982.34,4658.39 1982.34,4650.47 2007.14,4625.67 2005.95,4625.67 L3819.2@2005.95,4624.49
RF_BC0_PRX_DPX_LNA_LB_RXP: C3807.1 DPX3802.8 L3819.1 | length 97
  Top w4: DPX3802.8@1981.56,4683.49 1979.29,4683.49 1966.58,4670.78 1966.58,4648.46 1985.95,4629.09 L3819.1@1985.95,4624.49 1985.95,4603.49 C3807.1@1984.95,4602.49
RF_BC0_PRX_MT6158_LNA_LB_RXN: C3808.2 L3820.2 U3701.B3 | length 114.1
  Top w4: U3701.B3@1926.43,4542.46 1930.53,4538.36 1984.31,4538.36 2005.95,4560 L3820.2@2005.95,4560.49 ; L3820.2@2004.95,4560.49 L3820.2@2005.95,4560.49 ; C3808.2@2006.95,4582.49 2005.95,4581.49 L3820.2@2005.95,4560.49
RF_BC0_PRX_MT6158_LNA_LB_RXP: C3807.2 L3820.1 U3701.B2 | length 92.1
  Top w4: U3701.B2@1926.43,4558.21 1937.55,4547.09 1972.55,4547.09 L3820.1@1985.95,4560.49 1985.95,4581.49 C3807.2@1984.95,4582.49
RF_BC0_TRX_ASM: R3815.1 U3801.3 | length 36.1
  Top w5: R3815.1@2102.31,4666.09 2110.3,4658.1 U3801.3@2110.3,4633.33
RF_BC0_TRX_ASM_1: L3821.1 R3813.1 R3815.2 | length 81.6
  Top w5: R3813.1@2065.31,4740.09 2086.31,4740.09 2099.31,4727.09 L3821.1@2099.31,4714.09 2099.31,4701.59 2102.31,4698.59 R3815.2@2102.31,4686.09
RF_BC0_TRX_DPX: DPX3802.6 L3816.1 R3813.2 | length 68.9
  Top w5: DPX3802.6@2012.95,4707.8 2014.31,4707.8 2014.31,4741.09 L3816.1@2013.31,4742.09 2017.31,4742.09 2019.31,4740.09 R3813.2@2045.31,4740.09
RF_BC0_TX_MT6158: C3904.1 U3701.A8 | length 299.6
  Top w5: U3701.A8@1942.18,4463.72 1974.68,4463.72 v1(1983.31,4455.09)
  Inner Layer 2 w4: v1(1983.31,4455.09) 1993.31,4445.09 v3(1993.31,4440.09)
  Inner Layer 4 w4: v3(1993.31,4440.09) 1985.31,4432.09 1985.31,4247.09 v3(1995.31,4237.09)
  Inner Layer 5 w4: v3(1995.31,4237.09) 1996.08,4237.86 v2(1996.08,4262.11)
RF_BC0_TX_PA: PA3901.2 R3902.2 | length 32.7
  Bottom w5: R3902.2@1955.08,4262.11 1955.08,4270.61 1966.94,4282.46 PA3901.2@1966.93,4289.88
RF_BC0_TX_PA_1: C3904.2 L3901.1 R3902.1 | length 44.4
  Bottom w5: R3902.1@1955.08,4242.11 1956.08,4243.11 1956.08,4241.11 L3901.1@1976.08,4241.11 C3904.2@1976.08,4262.11
RF_GSM900_PRX_MT6169_RFIN1_LB1: C3336.2 L3334.2 U3101.C14 | length 157.4
  Top w4: C3336.2@1935.65,3665.59 L3334.2@1935.65,3690.59 1935.65,3695.47 cw(c1953.51,3695.47) 1940.88,3708.09 1955.84,3723.05 ccw(c1936.97,3741.91) 1963.65,3741.91 1963.65,3750.59 cw(c1973.31,3750.59) 1966.48,3757.42 1972.46,3763.4 ccw(c1957.52,3778.34) 1978.65,3778.34 1978.65,3790.67 cw(c1984.55,3790.67) 1980.38,3794.84 U3101.C14@1989.64,3804.1
RF_GSM900_PRX_MT6169_RFIP1_LB1: C3328.2 L3334.1 U3101.D14 | length 161.4
  Top w4: C3328.2@1910.65,3665.59 1911.12,3666.05 ccw(c1900.16,3677.01) 1915.65,3677.01 L3334.1@1915.65,3690.59 1915.65,3695.59 1949,3728.93 ccw(c1935.34,3742.59) 1954.65,3742.59 1954.65,3751.43 cw(c1971.39,3751.43) 1959.56,3763.27 1965.96,3769.67 ccw(c1957.03,3778.59) 1969.65,3778.59 1969.65,3794.59 cw(c1982.37,3794.59) 1973.38,3803.58 U3101.D14@1973.9,3804.1
RF_GSM900_PRX_SAW: C3331.2 L3331.1 U3322.1 | length 63.9
  Top w5: C3331.2@1870.65,3545.59 1872.12,3544.13 ccw(c1880.65,3552.66) 1880.65,3540.59 L3331.1@1895.65,3540.59 1895.65,3541.59 cw(c1910.78,3541.59) 1900.08,3552.29 1905.45,3557.66 cw(c1920.42,3542.69) 1920.42,3563.86 U3322.1@1920.65,3563.86
RF_GSM900_PRX_SAW_RFIN1: C3336.1 L3333.2 U3322.3 | length 50.2
  Top w4: U3322.3@1931.97,3597.36 1930.65,3598.68 L3333.2@1930.65,3620.59 1930.65,3633.8 cw(c1947.05,3633.8) 1935.46,3645.39 C3336.1@1935.65,3645.59
RF_GSM900_PRX_SAW_RFIP1: C3328.1 L3333.1 U3322.4 | length 48.8
  Top w4: U3322.4@1909.33,3597.36 1910.65,3598.68 L3333.1@1910.65,3620.59 C3328.1@1910.65,3645.59
RF_GSM900_PRX_TXM: C3331.1 U3307.36 | length 589
  Top w5: C3331.1@1870.65,3525.59 1868.07,3523 ccw(c1871.48,3519.59) 1866.65,3519.59 1866.65,3376.59 ccw(c1881.65,3376.59) 1868.96,3368.59 1870.65,3366.91 ccw(c1878.65,3374.91) 1878.65,3363.59 2112.65,3363.59 ccw(c2112.65,3375.66) 2121.19,3367.13 2121.41,3367.35 ccw(c2111.17,3377.59) 2125.65,3377.59 2125.65,3505.59 cw(c2140.86,3505.59) 2130.11,3516.34 2141.01,3527.24 U3307.36@2149.27,3527.24
RF_HB1_TX_1: C3256.2 R3230.1 R3231.1 | length 50
  Top w5: R3230.1@1845.65,3475.59 R3231.1@1845.65,3500.59 C3256.2@1845.65,3525.59
RF_HB1_TX_MT6169: C3256.1 U3101.F15 | length 278.6
  Top w5: C3256.1@1845.65,3545.59 1877.33,3577.26 ccw(c1842.74,3611.85) 1891.65,3611.85 1891.65,3677.59 cw(c1921.23,3677.59) 1900.32,3698.51 1936.31,3734.5 ccw(c1921.62,3749.2) 1942.4,3749.2 U3101.F15@1942.4,3788.35
RF_HB1_TX_PA: R3201.1 R3230.2 U3203.3 | length 101.5
  Top w4: R3201.1@1845.65,3430.59 v1(1845.65,3430.73)
  Top w5: v1(1845.65,3430.73) R3230.2@1845.65,3455.59
  Inner Layer 2 w3: v3(1845.65,3415.59) v1(1845.65,3430.73)
  Inner Layer 5 w4: v3(1845.65,3415.59) v2(1845.65,3434.59)
  Bottom w5: v2(1845.65,3434.59) 1848.66,3437.6 U3203.3@1886.76,3437.6
RF_HB2_TX_1: C3251.2 C3252.1 L3238.2 | length 84.3
  Top w5: L3238.2@1795.65,3450.59 C3251.2@1795.65,3475.59 1795.65,3490.59 cw(c1819.8,3490.59) 1802.72,3507.66 C3252.1@1820.65,3525.59
RF_HB2_TX_MT6169: C3252.2 U3101.F14 | length 305.2
  Top w3: 1925.65,3742.64 1929.1,3746.09 ccw(c1920.54,3754.66) 1932.65,3754.66 1932.65,3792.59 cw(c1936.91,3792.59) 1933.9,3795.6 U3101.F14@1942.4,3804.1
  Top w5: C3252.2@1820.65,3545.59 1869.82,3594.76 ccw(c1848.5,3616.08) 1878.65,3616.08 1878.65,3679.1 cw(c1918.58,3679.1) 1890.35,3707.33 1925.65,3742.64
RF_HB2_TX_PA: C3250.2 L3238.1 U3203.4 | length 109.1
  Top w5: L3238.1@1795.65,3430.59 C3250.2@1820.65,3430.59 v1(1820.65,3430.5)
  Inner Layer 2 w3: v1(1820.65,3430.5) v3(1820.65,3445.59)
  Inner Layer 5 w4: v3(1820.65,3445.59) 1821.65,3445.59 ccw(c1821.65,3469.73) 1838.72,3452.66 v2(1839.65,3453.59)
  Bottom w5: v2(1839.65,3453.59) 1840.98,3454.92 U3203.4@1886.76,3454.92
RF_HB_DRX_DIPLEXER: C3499.1 DIPX3801.3 | length 556.1
  Top w5: v1(2125.6,4431.68) 2126.01,4432.09 2127.33,4432.09 v1(2125.6,4431.68)
  Inner Layer 2 w4: v3(2110.31,4429.09) 2113.31,4432.09 2125.19,4432.09 v1(2125.6,4431.68)
  Inner Layer 5 w3: v2(2096.65,4417.59) 2097.19,4417.05 2109.77,4429.63 v3(2110.31,4429.09)
  Bottom w5: v2(2096.65,4417.59) 2096.65,4352.89 ccw(c2191.54,4352.89) 2124.44,4285.8 2129.81,4280.43 ccw(c2146.18,4296.8) 2146.18,4273.65 2156.68,4273.65 cw(c2156.68,4239.53) 2180.81,4263.66 2268.94,4175.52 cw(c2249.32,4155.89) 2277.07,4155.89 2277.07,4006.51 C3499.1@2264.15,3993.59
RF_LB3_TX_1: R3328.1 R3334.1 U3307.2 | length 63
  Top w5: R3334.1@2163.65,3400.59 2163.65,3422.59 R3328.1@2160.65,3425.59 2163.33,3428.27 ccw(c2135.01,3456.59) 2175.06,3456.59 U3307.2@2175.06,3458.15
RF_LB3_TX_MT6169: C3334.2 U3101.J15 | length 141.8
  Top w5: C3334.2@1800.65,3695.59 1809.53,3704.47 ccw(c1804.41,3709.59) 1811.65,3709.59 1811.65,3718.59 cw(c1823.72,3718.59) 1815.19,3727.13 1825.41,3737.35 cw(c1835.65,3727.1) 1835.65,3741.59 1844.02,3741.59 ccw(c1844.02,3756.4) 1854.5,3745.93 1895.16,3786.59 U3101.J15@1895.16,3788.35
RF_LB4_TX_1: C3225.1 R3214.2 R3226.1 | length 59.6
  Top w5: R3214.2@1800.65,3645.59 1800.7,3645.64 ccw(c1788.75,3657.59) 1805.65,3657.59 R3226.1@1805.65,3670.59 1805.65,3675.59 C3225.1@1825.65,3695.59
RF_LB4_TX_MT6169: C3225.2 U3101.H15 | length 116.8
  Top w5: C3225.2@1825.65,3715.59 1835.12,3725.05 cw(c1843.65,3716.52) 1843.65,3728.59 1849.65,3728.59 ccw(c1849.65,3742.81) 1859.71,3732.75 1910.9,3783.95 U3101.H15@1910.9,3788.35
RF_LB4_TX_PA: C3226.2 R3214.1 U3203.13 | length 112.8
  Top w4: v1(1825.65,3625.49) C3226.2@1825.65,3625.59
  Top w5: R3214.1@1800.65,3625.59 C3226.2@1825.65,3625.59
  Inner Layer 2 w3: v1(1825.65,3625.49) v3(1825.65,3640.59)
  Inner Layer 5 w4: v3(1825.65,3640.59) v2(1848.65,3640.59)
  Bottom w5: v2(1848.65,3640.59) 1848.65,3639.34 1871.87,3616.12 ccw(c1878.01,3622.26) 1878.01,3613.58 U3203.13@1886.76,3613.58
RF_MB1_TX_1: C3314.1 R3306.1 R3333.2 | length 477.9
  Top w5: C3314.1@1800.65,3370.59 C3314.1@1801.23,3370.02 ; C3314.1@1801.24,3370.01 ccw(c1809.5,3378.29) 1809.5,3366.59 v1(1814.65,3366.59) ; v1(2179.65,3400.59) R3306.1@2188.65,3400.59 2188.65,3422.59 R3333.2@2185.65,3425.59
  Inner Layer 2 w3: v1(1814.65,3366.59) 1822.65,3358.59 v3(1827.65,3358.59) ; v3(2167.65,3357.59) 2180.41,3370.35 2180.41,3399.83 v1(2179.65,3400.59)
  Inner Layer 5 w3: v3(1827.65,3358.59) 1849.95,3336.29 2155.35,3336.29 2162.7,3343.64 ccw(c2150.75,3355.59) 2167.65,3355.59 v3(2167.65,3357.59)
RF_MB1_TX_MT6169: C3314.2 U3101.G14 | length 476.3
  Top w3: 1922.65,3758.59 1923.46,3759.4 ccw(c1915.76,3767.1) 1926.65,3767.1 U3101.G14@1926.65,3804.1
  Top w5: C3314.2@1800.65,3390.59 1784.9,3406.35 cw(c1795.14,3416.59) 1780.65,3416.59 1780.65,3507.59 cw(c1828.94,3507.59) 1794.79,3541.73 1860,3606.93 ccw(c1846.34,3620.59) 1865.65,3620.59 1865.65,3682.59 cw(c1911.52,3682.59) 1879.09,3715.03 1922.65,3758.59
RF_MB1_TX_PA: R3333.1 U3307.3 | length 36.7
  Top w5: U3307.3@2193.96,3458.15 2193.96,3447.49 ccw(c2210.63,3447.49) 2198.84,3435.71 2205.65,3428.9 R3333.1@2205.65,3425.59
RF_MB2_TX_1: C3217.1 C3254.2 L3215.2 | length 50
  Top w5: L3215.2@1850.65,3645.59 C3254.2@1850.65,3670.59 C3217.1@1850.65,3695.59
RF_MB2_TX_MT6169: C3217.2 U3101.H14 | length 126.6
  Top w3: U3101.H14@1910.9,3804.1 1919.19,3795.82 cw(c1915.64,3792.28) 1920.65,3792.28 1920.65,3778.59 cw(c1912.74,3778.59) 1918.34,3773 1915.74,3770.4
  Top w5: C3217.2@1850.65,3715.59 1856.65,3715.59 ccw(c1856.65,3725.91) 1863.95,3718.61 1915.74,3770.4
RF_MB2_TX_PA: C3228.2 L3215.1 U3203.12 | length 166.6
  Top w5: v1(1825.65,3600.59) C3228.2@1826.65,3600.59 ; L3215.1@1850.65,3625.59 L3215.1@1850.65,3624.94 ; C3228.2@1826.65,3600.59 ccw(c1826.65,3619.9) 1840.31,3606.25 ; C3228.2@1826.65,3600.59 ccw(c1826.65,3619.9) 1840.31,3606.25 ; 1840.31,3606.25 1844.75,3610.69 ; 1844.76,3610.69 ccw(c1830.49,3624.94) L3215.1@1850.65,3624.94 ; 1844.76,3610.69 ccw(c1830.49,3624.94) L3215.1@1850.65,3624.94
  Inner Layer 2 w3: v3(1809.65,3600.59) v1(1825.65,3600.59)
  Inner Layer 5 w4: v3(1809.65,3600.59) 1809.65,3599.09 1827.65,3599.09 v2(1827.65,3597.59)
  Bottom w5: v2(1827.65,3597.59) 1828.98,3596.26 U3203.12@1886.76,3596.26
RF_RX1_BBIN: U1001.AJ7 U3101.N7 | length 518.3
  Top w4: v1(1812.62,3900.6) 1812.61,3900.44 1818.11,3900.44 1832.01,3914.34 U3101.N7@1832.16,3914.34 ; v4(1423.68,3763.76) 1423.88,3763.96 1424.01,3764.09 1423.8,3764.09 1423.75,3763.96 v4(1423.68,3763.76) ; v4(1423.68,3763.76) 1423.67,3763.96 v4(1423.68,3763.76)
  Inner Layer 2 w4: v4(1423.68,3763.76) 1426.45,3760.97 1485.35,3760.97 1532.19,3714.13 1629.67,3714.13 1720.01,3804.47 1720.01,3804.55 1793.95,3878.48 1793.95,3885.85 1800.98,3892.87 ; 1800.98,3892.87 1801.94,3893.83 1805.84,3893.83 1812.45,3900.44 1812.61,3900.28 v1(1812.62,3900.6)
RF_RX1_BBIN_C2K: TP3715.1 U1001.AH13 U3701.J9 | length 1338.5
  Inner Layer 2 w4: v4(1407.93,3858.25) 1421.77,3872.09 v3(1436.31,3872.09) ; v3(1796.57,4441.26) 1809.47,4441.26 v4(1816.19,4447.97)
  Inner Layer 4 w4: v3(1436.31,3872.09) 1436.47,3872.09 1443.23,3878.85 1443.23,3979.45 1564.67,4100.89 1564.67,4211.17 1751.63,4398.13 1765.88,4398.13 1796.57,4428.82 v3(1796.57,4441.26)
  Inner Layer 5 w4: v2(1782.3,4425.09) 1787.31,4425.09 1796.57,4434.34 v3(1796.57,4441.26)
  Bottom w4: v2(1759.31,4472.09) 1779.31,4452.09 1819.47,4452.09 1827.49,4444.07 ; v2(1782.3,4425.09) 1818.45,4425.09 1827.49,4434.13 1827.49,4444.07 ; 1768.24,4562.9 1774.43,4569.09 1793.27,4569.09 1800.31,4562.05 1800.31,4524.51 ; 1768.24,4562.9 v2(1723.17,4517.83) 1755.07,4517.83 1772.81,4500.09 1786.72,4500.09 1803.58,4516.95 ; 1768.24,4562.9 1768.24,4539.19 1783.34,4524.09 1799.89,4524.09 1800.31,4524.51 ; 1800.31,4524.51 1800.31,4520.22 1803.58,4516.95 ; 1803.58,4516.95 1808.44,4512.09 1815.27,4512.09 1827.49,4499.87 1827.49,4444.07
RF_RX1_BBIP: U1001.AH7 U3101.N8 | length 530.3
  Top w4: v1(1805.95,3880.87) 1813.52,3888.44 1817.42,3888.44 1827.57,3898.59 U3101.N8@1832.16,3898.59 ; v4(1407.93,3763.76) 1408.26,3764.09 v4(1407.93,3763.76)
  Inner Layer 2 w4: v4(1407.93,3763.76) 1422.76,3748.92 1485.31,3748.92 1528.14,3706.09 1529,3706.09 1529.04,3706.13 1632.98,3706.13 1728.01,3801.16 1728.01,3801.23 1802.02,3875.24 1802.09,3875.24 1806.47,3879.62 1806.47,3880.35 v1(1805.95,3880.87)
RF_RX1_BBIP_C2K: TP3714.1 U1001.AJ13 U3701.J8 | length 845.7
  Top w4: U1001.AJ13@1423.46,3858.24 v4(1423.68,3858.25) U1001.AJ13@1423.46,3858.24
  Inner Layer 2 w4: v4(1423.68,3858.25) 1423.67,3857.09 1430.87,3857.09 1437.09,3850.87 1439.09,3848.86 v3(1436.31,3850.09) ; v3(1800.3,4463.09) 1800.3,4462.16 1800.82,4462.15 1800.94,4463 1801.16,4464.53 v4@1816.2,4464.53
  Inner Layer 4 w4: v3(1436.31,3850.09) 1451.39,3865.16 1451.39,3976.25 1572.67,4097.53 1572.67,4207.85 1753.35,4388.54 1767.6,4388.54 1811.57,4432.51 1811.57,4447.95 1800.3,4459.22 v3(1800.3,4463.09)
  Inner Layer 5 w4: v2(1781.31,4470.09) 1793.3,4470.09 v3(1800.3,4463.09)
  other v4: 1816.19,4463.72
RF_RX1_BBQN: U1001.AL6 U3101.M7 | length 495.3
  Top w3: U1001.AL6@1455.17,3748.01 1484.04,3748.01 1484.12,3748.09 1506.56,3748.09 1514.3,3740.35 1514.3,3739.77
  Top w4: 1514.3,3739.77 1531.99,3722.09 1590.31,3722.09 v1(1602.31,3734.09)
  Inner Layer 2 w4: v1(1602.31,3734.09) 1606.31,3738.09 1617.37,3738.09 1617.58,3738.3 1631.21,3738.3 1704.01,3811.1 1704.01,3811.17 1777.95,3885.11 1777.95,3892.47 1777.95,3893.9 1792.62,3908.57 1792.62,3908.89 1804.33,3920.6 1804.66,3920.6 1806.13,3922.08 1840.17,3922.08 v4(1847.91,3914.34)
RF_RX1_BBQN_C2K: TP3717.1 U1001.AG14 U3701.K8 | length 803.7
  Top w4: v1(1781.3,4456.09) 1781.3,4456.72 1788.3,4463.72 U3701.K8@1800.45,4463.72 ; U1001.AG14@1391.69,3874.48 v4(1392.18,3873.99) 1392.18,3874.96 U1001.AG14@1391.7,3874.49
  Inner Layer 2 w4: v4(1392.18,3873.99) 1399.18,3880.99 v3@1399.18,3886.98 ; v3(1397.31,3888.09) v3@1398.07,3888.09 ; v3(1766.31,4450.09) 1772.31,4456.09 v1(1781.3,4456.09) ; v3@1398.07,3888.09 v3@1399.18,3886.98 ; v3@1398.07,3888.09 1399.18,3888.09 v3@1399.18,3886.98
  Inner Layer 4 w4: v3(1397.31,3888.09) 1406.03,3888.09 1417.41,3899.47 1417.41,3987.66 1540.67,4110.91 1540.67,4221.54 1746.61,4427.48 1746.61,4432.6 1764.1,4450.09 v3(1766.31,4450.09)
  Inner Layer 5 w4: v2(1747.08,4450.11) v3(1766.31,4450.09)
  Bottom w4: v2(1747.08,4450.11) TP3717.1@1747.31,4450.09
